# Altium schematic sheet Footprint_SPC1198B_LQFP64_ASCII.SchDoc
size A4
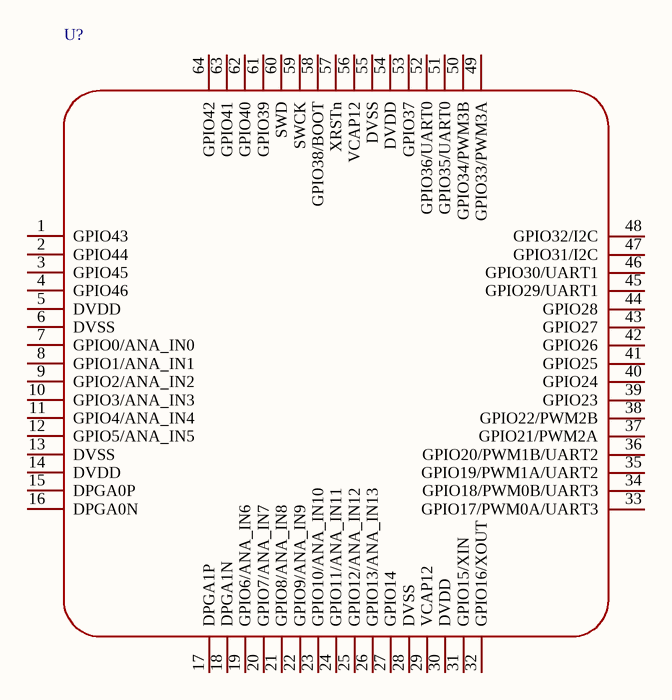
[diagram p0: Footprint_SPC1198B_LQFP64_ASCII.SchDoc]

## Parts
U?  SPC1135_LQFP64  [LQFP-64_L10.0-W10.0-P0.50-LS12.0-TL]  (value not drawn)

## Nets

Not connected (* = marked no-connect by the designer): U? 1(GPIO43) 2(GPIO44) 3(GPIO45) 4(GPIO46) 5(DVDD) 6(DVSS) 7(GPIO0/ANA_IN0) 8(GPIO1/ANA_IN1) 9(GPIO2/ANA_IN2) 10(GPIO3/ANA_IN3) 11(GPIO4/ANA_IN4) 12(GPIO5/ANA_IN5) 13(DVSS) 14(DVDD) 15(DPGA0P) 16(DPGA0N) 17(DPGA1P) 18(DPGA1N) 19(GPIO6/ANA_IN6) 20(GPIO7/ANA_IN7) 21(GPIO8/ANA_IN8) 22(GPIO9/ANA_IN9) 23(GPIO10/ANA_IN10) 24(GPIO11/ANA_IN11) 25(GPIO12/ANA_IN12) 26(GPIO13/ANA_IN13) 27(GPIO14) 28(DVSS) 29(VCAP12) 30(DVDD) 31(GPIO15/XIN) 32(GPIO16/XOUT) 33(GPIO17/PWM0A/UART3) 34(GPIO18/PWM0B/UART3) 35(GPIO19/PWM1A/UART2) 36(GPIO20/PWM1B/UART2) 37(GPIO21/PWM2A) 38(GPIO22/PWM2B) 39(GPIO23) 40(GPIO24) 41(GPIO25) 42(GPIO26) 43(GPIO27) 44(GPIO28) 45(GPIO29/UART1) 46(GPIO30/UART1) 47(GPIO31/I2C) 48(GPIO32/I2C) 49(GPIO33/PWM3A) 50(GPIO34/PWM3B) 51(GPIO35/UART0) 52(GPIO36/UART0) 53(GPIO37) 54(DVDD) 55(DVSS) 56(VCAP12) 57(XRSTn) 58(GPIO38/BOOT) 59(SWCK) 60(SWD) 61(GPIO39) 62(GPIO40) 63(GPIO41) 64(GPIO42)

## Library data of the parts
U? = SPC1135_LQFP64: Add into BOM: yes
